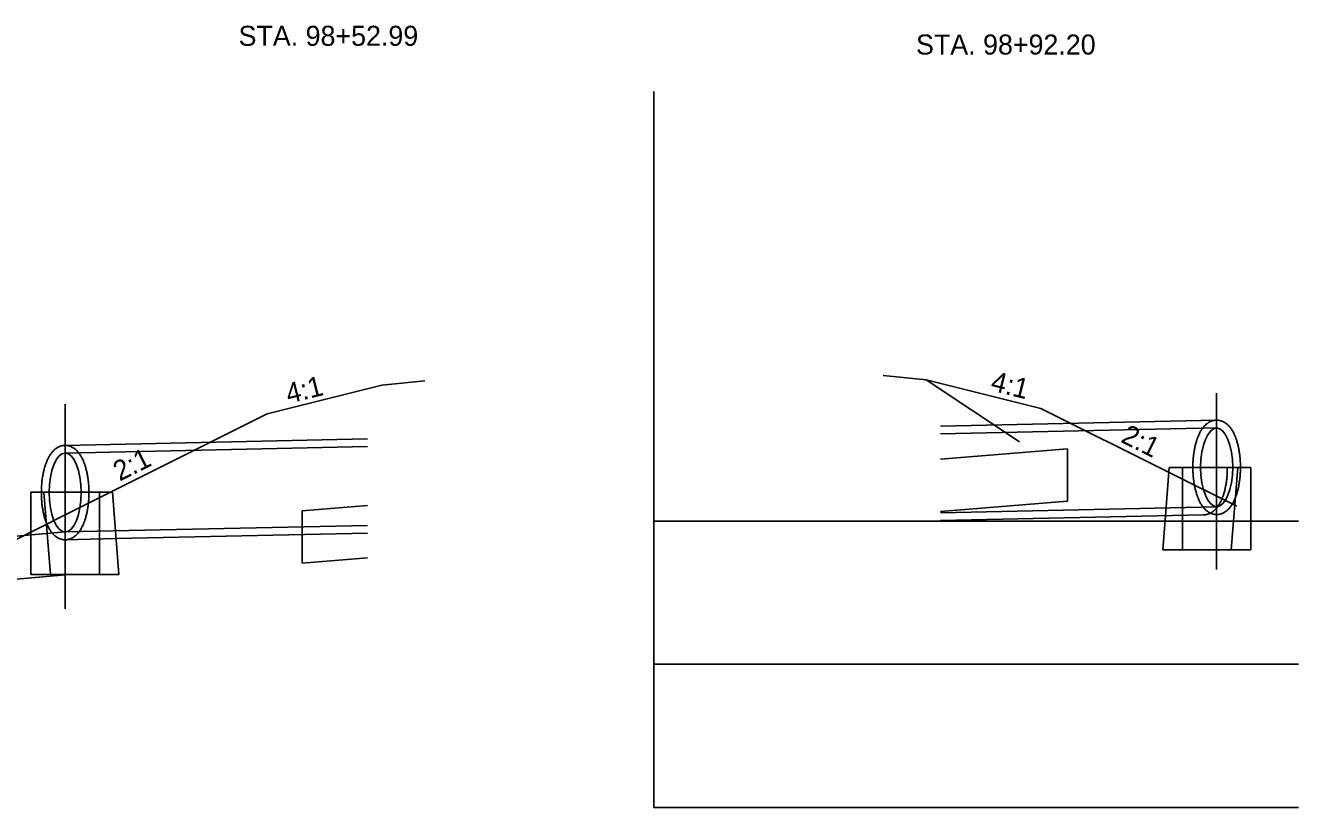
# Model space of a CAD drawing. Extents: x -8.7 to 76.9, y -12.1 to 38.2.
# Drawn here: x 1.19 to 18.97, y -12.08 to -1.16 of the extents above; entities that cross this region are included whole.
import ezdxf

# ---------------------------------------------------------------- set-up
doc = ezdxf.new("R2010")
doc.units = 0
for name, color, linetype in [('DR_P_Culvert', 7, 'Continuous'), ('DR_P_Erosion_Control', 7, 'Continuous'), ('DR_P_Headwall', 7, 'Continuous'), ('DR_X_Culvert', 7, 'Continuous'), ('SH_Major_Grid_Line', 7, 'Continuous'), ('SH_Text', 7, 'Continuous'), ('XS_P_Finished_Grade', 7, 'Continuous')]:
    doc.layers.add(name, color=color, linetype=linetype)

msp = doc.modelspace()

# ---------------------------------------------------------------- linework, layer by layer
at = {"layer": 'DR_P_Culvert'}
for p, q in [((13.967, -6.759), (17.824, -6.675)), ((13.967, -6.867), (17.824, -6.783)), ((1.745, -7.027), (5.967, -6.934)), ((1.745, -7.135), (5.967, -7.043)), ((13.967, -7.968), (17.824, -7.883)), ((13.967, -8.076), (17.641, -7.996)), ((1.745, -8.235), (5.967, -8.143)), ((1.745, -8.344), (2.457, -8.326)), ((2.457, -8.326), (5.967, -8.25))]:
    msp.add_line(p, q, dxfattribs=at)
for centre, major_axis in [((17.824, -7.333), (0, 0.55)), ((1.745, -7.685), (0, -0.55))]:
    msp.add_ellipse(centre, major_axis=major_axis, ratio=0.406586, dxfattribs=at)
for points in [[(18.156, -7.333), (18.156, -7.373), (18.155, -7.412), (18.148, -7.488), (18.144, -7.526), (18.132, -7.598), (18.124, -7.633), (18.106, -7.701), (18.095, -7.733), (18.077, -7.778), (18.07, -7.793), (18.056, -7.821), (18.049, -7.835), (18.033, -7.86), (18.025, -7.873), (18.007, -7.896), (17.997, -7.907), (17.977, -7.928), (17.966, -7.938), (17.942, -7.956), (17.929, -7.964), (17.909, -7.974), (17.902, -7.977), (17.887, -7.982), (17.879, -7.984), (17.864, -7.988), (17.856, -7.99), (17.84, -7.992), (17.832, -7.992), (17.824, -7.992), (17.816, -7.992), (17.808, -7.992), (17.792, -7.99), (17.784, -7.988), (17.768, -7.984), (17.761, -7.982), (17.746, -7.977), (17.739, -7.974), (17.718, -7.964), (17.706, -7.956), (17.682, -7.938), (17.671, -7.928), (17.65, -7.907), (17.641, -7.896), (17.623, -7.873), (17.615, -7.86), (17.599, -7.835), (17.592, -7.821), (17.578, -7.793), (17.571, -7.778), (17.553, -7.733), (17.542, -7.701), (17.524, -7.633), (17.516, -7.598), (17.504, -7.526), (17.499, -7.488), (17.493, -7.412), (17.491, -7.373), (17.491, -7.294), (17.493, -7.255), (17.499, -7.179), (17.504, -7.141), (17.516, -7.068), (17.524, -7.033), (17.542, -6.966), (17.553, -6.934), (17.571, -6.888), (17.578, -6.874), (17.592, -6.845), (17.599, -6.832), (17.615, -6.806), (17.623, -6.794), (17.641, -6.77), (17.65, -6.759), (17.671, -6.739), (17.682, -6.729), (17.706, -6.711), (17.718, -6.703), (17.739, -6.693), (17.746, -6.69), (17.761, -6.685), (17.768, -6.682), (17.784, -6.678), (17.792, -6.677), (17.808, -6.675), (17.816, -6.675), (17.824, -6.675)], [(17.824, -6.675), (17.832, -6.675), (17.84, -6.675), (17.856, -6.677), (17.864, -6.678), (17.879, -6.682), (17.887, -6.685), (17.902, -6.69), (17.909, -6.693), (17.929, -6.703), (17.942, -6.711), (17.966, -6.729), (17.977, -6.739), (17.997, -6.759), (18.007, -6.77), (18.025, -6.794), (18.033, -6.806), (18.049, -6.832), (18.056, -6.845), (18.07, -6.874), (18.077, -6.888), (18.095, -6.934), (18.106, -6.966), (18.124, -7.033), (18.132, -7.068), (18.144, -7.141), (18.148, -7.179), (18.155, -7.255), (18.156, -7.294), (18.156, -7.333), (18.156, -7.333), (18.156, -7.333)], [(1.745, -8.344), (1.754, -8.344), (1.762, -8.344), (1.778, -8.342), (1.786, -8.34), (1.801, -8.336), (1.809, -8.334), (1.823, -8.329), (1.83, -8.326), (1.851, -8.315), (1.864, -8.307), (1.887, -8.29), (1.898, -8.28), (1.919, -8.259), (1.928, -8.248), (1.946, -8.225), (1.955, -8.212), (1.97, -8.187), (1.978, -8.173), (1.992, -8.145), (1.998, -8.13), (2.017, -8.085), (2.027, -8.053), (2.046, -7.985), (2.053, -7.95), (2.065, -7.878), (2.07, -7.84), (2.076, -7.764), (2.078, -7.725), (2.078, -7.646), (2.076, -7.607), (2.07, -7.53), (2.065, -7.493), (2.053, -7.42), (2.046, -7.385), (2.027, -7.318), (2.017, -7.286), (1.998, -7.24), (1.992, -7.225), (1.978, -7.197), (1.97, -7.184), (1.955, -7.158), (1.946, -7.146), (1.928, -7.122), (1.919, -7.111), (1.898, -7.09), (1.887, -7.081), (1.864, -7.063), (1.851, -7.055), (1.83, -7.045), (1.823, -7.042), (1.809, -7.036), (1.801, -7.034), (1.786, -7.03), (1.778, -7.029), (1.762, -7.027), (1.754, -7.026), (1.737, -7.026), (1.729, -7.027), (1.713, -7.029), (1.705, -7.03), (1.69, -7.034), (1.682, -7.036), (1.668, -7.042), (1.66, -7.045), (1.64, -7.055), (1.627, -7.063), (1.603, -7.081), (1.592, -7.09), (1.572, -7.111), (1.563, -7.122), (1.545, -7.146), (1.536, -7.158), (1.521, -7.184), (1.513, -7.197), (1.499, -7.225), (1.493, -7.24), (1.474, -7.286), (1.464, -7.318), (1.445, -7.385), (1.438, -7.42), (1.425, -7.493), (1.421, -7.53), (1.415, -7.607), (1.413, -7.646), (1.413, -7.725), (1.415, -7.764), (1.421, -7.84), (1.425, -7.878), (1.438, -7.95), (1.445, -7.985), (1.464, -8.053), (1.474, -8.085), (1.493, -8.13), (1.499, -8.145), (1.513, -8.173), (1.521, -8.187), (1.536, -8.212), (1.545, -8.225), (1.563, -8.248), (1.572, -8.259), (1.592, -8.28), (1.603, -8.29), (1.627, -8.307), (1.64, -8.315), (1.66, -8.326), (1.668, -8.329), (1.682, -8.334), (1.69, -8.336), (1.705, -8.34), (1.713, -8.342), (1.729, -8.344), (1.737, -8.344), (1.745, -8.344)]]:
    msp.add_open_spline(points, degree=3, dxfattribs=at)
at = {"layer": 'DR_P_Erosion_Control'}
msp.add_lwpolyline([(-2.433, -8.606), (1.745, -8.235), (1.745, -8.835), (-2.433, -9.206)], close=True, dxfattribs=at)
at = {"layer": 'DR_P_Headwall'}
for p, q in [((17.109, -8.009), (17.163, -7.333)), ((17.163, -7.333), (17.346, -7.333)), ((17.346, -8.483), (17.346, -7.333)), ((17.346, -7.333), (17.491, -7.333)), ((17.491, -7.333), (17.973, -7.333)), ((17.973, -7.333), (18.119, -7.333)), ((18.028, -8.483), (18.119, -7.333)), ((18.119, -7.333), (18.302, -7.333)), ((18.302, -8.483), (18.302, -7.333)), ((1.268, -8.831), (1.268, -7.681)), ((1.413, -7.681), (1.268, -7.681)), ((2.078, -7.681), (1.413, -7.681)), ((1.542, -8.831), (1.45, -7.681)), ((2.223, -7.681), (2.078, -7.681)), ((2.223, -8.831), (2.223, -7.681)), ((2.406, -7.681), (2.223, -7.681)), ((2.497, -8.831), (2.406, -7.681)), ((17.072, -8.483), (17.109, -8.009)), ((17.072, -8.483), (18.302, -8.483)), ((2.223, -8.831), (1.268, -8.831)), ((2.497, -8.831), (2.223, -8.831))]:
    msp.add_line(p, q, dxfattribs=at)
msp.add_open_spline([(17.973, -7.333), (17.973, -7.377), (17.972, -7.416), (17.966, -7.492), (17.961, -7.53), (17.949, -7.602), (17.941, -7.637), (17.923, -7.705), (17.912, -7.737), (17.894, -7.783), (17.887, -7.797), (17.873, -7.825), (17.866, -7.839), (17.85, -7.865), (17.842, -7.877), (17.824, -7.9), (17.814, -7.911), (17.794, -7.932), (17.783, -7.942), (17.759, -7.96), (17.747, -7.968), (17.726, -7.978), (17.719, -7.981), (17.704, -7.986), (17.697, -7.989), (17.681, -7.992), (17.673, -7.994), (17.657, -7.996), (17.649, -7.996), (17.641, -7.996)], degree=3, dxfattribs=at)
at = {"layer": 'DR_X_Culvert'}
for p, q in [((15.741, -7.074), (13.967, -7.217)), ((15.741, -7.807), (15.741, -7.074)), ((15.741, -7.807), (13.967, -7.951)), ((5.967, -7.864), (5.057, -7.938)), ((5.057, -8.671), (5.057, -7.938)), ((5.967, -8.598), (5.057, -8.671))]:
    msp.add_line(p, q, dxfattribs=at)
at = {"layer": 'SH_Major_Grid_Line'}
for p, q in [((9.967, -12.083), (9.967, -2.083)), ((9.967, -12.083), (9.967, -2.083)), ((17.824, -7.871), (17.824, -6.299)), ((1.745, -9.311), (1.745, -6.449)), ((17.824, -8.761), (17.824, -7.883)), ((9.967, -8.083), (18.967, -8.083)), ((9.967, -10.083), (18.967, -10.083)), ((9.967, -12.083), (18.967, -12.083))]:
    msp.add_line(p, q, dxfattribs=at)
at = {"layer": 'XS_P_Finished_Grade'}
for p, q in [((6.167, -6.186), (4.567, -6.586)), ((6.767, -6.126), (6.167, -6.186)), ((13.167, -6.049), (13.767, -6.109)), ((13.767, -6.109), (15.367, -6.509)), ((13.767, -6.109), (15.072, -6.978)), ((15.367, -6.509), (17.159, -7.404)), ((4.567, -6.586), (2.377, -7.681)), ((17.159, -7.404), (18.104, -7.877)), ((2.377, -7.681), (0.735, -8.502))]:
    msp.add_line(p, q, dxfattribs=at)

# ---------------------------------------------------------------- texts
at = {"layer": 'SH_Text'}
for s, p in [('STA. 98+52.99', (4.167, -1.447)), ('STA. 98+92.20', (13.626, -1.569))]:
    msp.add_text(s, height=0.27999, dxfattribs=at).set_placement(p)
for s, rotation, p in [('4:1', 345.9638, (14.654, -6.256)), ('4:1', 14.0362, (4.865, -6.446)), ('2:1', 333.4349, (16.471, -6.973)), ('2:1', 26.5651, (2.506, -7.533))]:
    msp.add_text(s, height=0.28, rotation=rotation, dxfattribs=at).set_placement(p)

doc.saveas('drawing.dxf')
